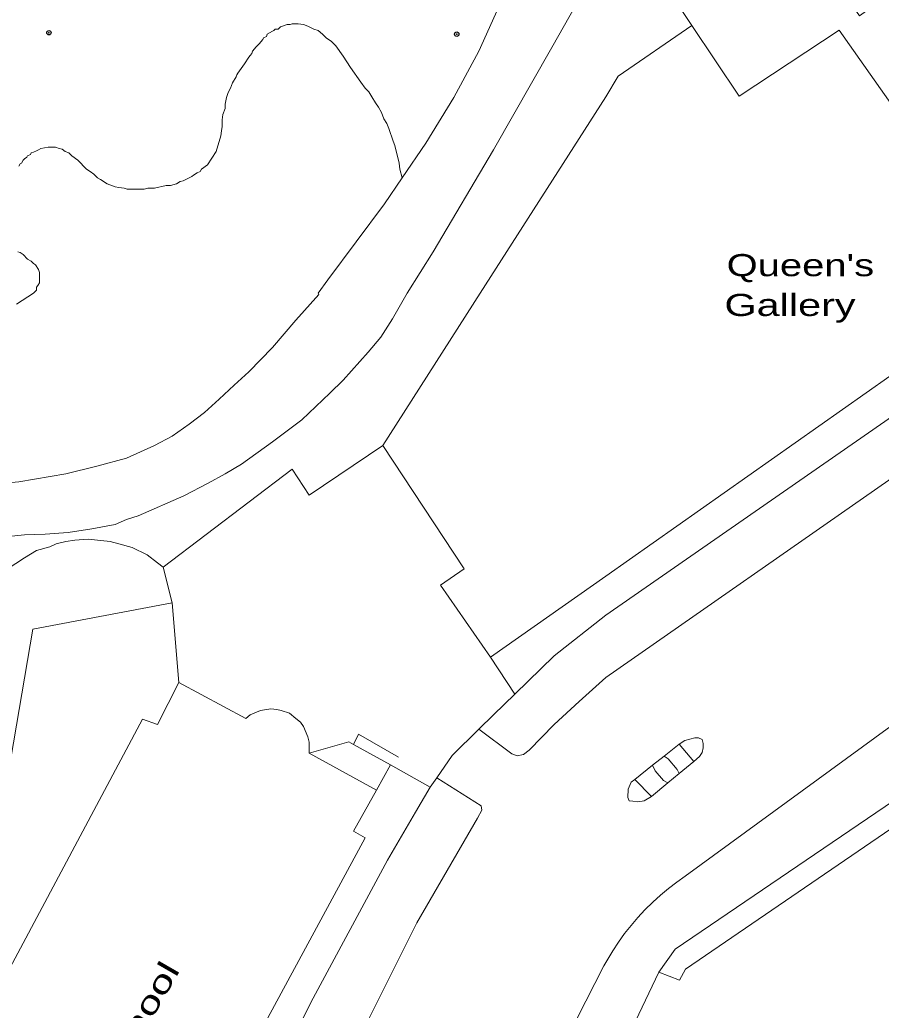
# Model space of a CAD drawing. Extents: x 528790 to 529292, y 179350 to 179856.
# Drawn here: x 528960.3 to 529018.7, y 179451.4 to 179518.5 of the extents above; entities that cross this region are included whole.
import ezdxf

# ---------------------------------------------------------------- set-up
doc = ezdxf.new("R2010")
doc.units = 0
doc.header["$LTSCALE"] = 0.6
doc.header["$PDMODE"] = 32
doc.header["$PDSIZE"] = 0.3
doc.layers.add('1', color=7, linetype='Continuous', lineweight=13)
doc.layers.add('2', color=7, linetype='Continuous', lineweight=13)
doc.layers.add('3', color=7, linetype='Continuous')
doc.layers.add('5', color=7, linetype='Continuous')

msp = doc.modelspace()

# ---------------------------------------------------------------- linework, layer by layer
at = {"layer": '1'}
for points in [[(529073.95, 179531.9), (529070.6, 179529.65), (529065.42, 179526.17), (529064.07, 179524.62), (529047.17, 179512.85), (529035.4, 179502.75), (529031.5, 179500), (529020.564, 179492.414), (529000, 179478.15), (528996.5, 179475.4), (528993.832, 179472.797), (528992.4, 179471.4), (528991.407, 179470.425), (528993.641, 179468.76), (528994.001, 179468.622), (528994.425, 179468.717), (528994.8, 179469), (528996.5, 179470.75), (528998.2, 179472.3), (529000, 179473.93), (529019.2, 179487.3), (529029.2, 179494.15), (529037.35, 179500), (529076.8, 179527.1)], [(529076.8, 179527.1), (529037.35, 179500), (529029.2, 179494.15), (529019.2, 179487.3), (529000, 179473.93), (528998.2, 179472.3), (528996.5, 179470.75), (528994.8, 179469), (528994.425, 179468.717), (528994.001, 179468.622), (528993.641, 179468.76), (528991.407, 179470.425), (528989.6, 179468.65), (528988.542, 179467.133), (528991.564, 179465.226), (528991.609, 179464.932), (528991.3, 179464.4), (528987.2, 179457.3), (528981.95, 179446.8)], [(528995.6, 179525.75), (528991.4, 179516.4), (528989.7, 179513.25), (528987.8, 179510.15), (528986.2, 179507.8), (528985, 179506.05), (528981.15, 179500.9), (528980.5, 179500), (528980.55, 179499.9), (528979, 179498.15), (528977.4, 179496.3), (528975.8, 179494.65), (528974.8, 179493.75), (528973.8, 179492.8), (528972.8, 179491.9), (528971.75, 179491.1), (528970.6, 179490.3), (528969.4, 179489.65), (528967.5, 179488.8), (528965.5, 179488.25), (528963.4, 179487.75), (528960.2, 179487.2)], [(528965.55, 179507.8), (528965.75, 179507.7), (528966.2, 179507.4), (528966.75, 179507.2), (528967, 179507.15), (528967.35, 179507.1), (528967.55, 179507.05), (528968.7, 179507.05), (528968.95, 179507.1), (528969.4, 179507.1), (528970.2, 179507.3), (528970.5, 179507.3), (528970.9, 179507.4), (528971.15, 179507.55), (528971.35, 179507.6), (528971.95, 179507.9), (528972.05, 179508), (528972.3, 179508.15), (528972.5, 179508.25), (528972.6, 179508.4), (528973, 179508.7), (528973.6, 179509.6), (528973.9, 179510.65), (528973.95, 179511), (528974, 179511.3), (528974, 179511.75), (528974.05, 179512.1), (528974.2, 179512.5), (528974.2, 179512.8), (528974.3, 179513.25), (528974.4, 179513.6), (528974.55, 179513.9), (528974.7, 179514.25), (528974.95, 179514.65), (528975, 179514.8), (528975.05, 179514.9), (528975.5, 179515.55), (528975.8, 179516), (528975.9, 179516.1), (528976, 179516.25), (528976.05, 179516.4), (528976.3, 179516.7), (528976.5, 179516.9), (528976.75, 179517.2), (528976.8, 179517.3), (528977, 179517.4), (528977.05, 179517.55), (528977.4, 179517.75), (528977.5, 179517.8), (528977.6, 179517.9), (528977.8, 179517.9), (528977.95, 179518.05), (528978.4, 179518.2), (528978.6, 179518.2), (528978.75, 179518.25), (528979.15, 179518.25), (528979.5, 179518.2), (528979.8, 179518.1), (528980.2, 179517.9), (528980.5, 179517.8), (528980.8, 179517.55), (528981.05, 179517.3), (528981.4, 179517.05), (528981.7, 179516.75), (528982.2, 179516.05), (528982.7, 179515.3), (528983.4, 179514.3), (528983.7, 179513.9), (528983.95, 179513.65), (528984.15, 179513.3), (528984.4, 179512.9), (528984.6, 179512.6), (528984.8, 179512.25), (528984.95, 179511.8), (528985.15, 179511.5), (528985.3, 179511.15), (528985.6, 179510.3), (528985.7, 179510), (528986, 179508.8), (528986.05, 179508.4), (528986.2, 179507.8), (528987.8, 179510.15), (528989.7, 179513.25), (528991.4, 179516.4), (528995.6, 179525.75)], [(528978.75, 179488.05), (528979.9, 179486.3), (528984.9, 179489.65), (528991.5, 179500), (529000, 179513.3), (529000.85, 179514.7), (529005.85, 179518.14), (529001.81, 179524.22), (529004.05, 179525.81)], [(528998.75, 179520.9), (528996.35, 179516.65), (528992.4, 179509.7), (528988.3, 179502.8), (528986.55, 179500), (528985.55, 179498.25), (528984.75, 179497), (528983.9, 179496), (528982.2, 179494.1), (528981.3, 179493.2), (528979.4, 179491.4), (528977.4, 179489.9), (528975.3, 179488.4), (528974.2, 179487.75), (528973.05, 179487.1), (528971.4, 179486.25), (528968.3, 179484.9), (528967.5, 179484.65), (528966.75, 179484.3), (528965.15, 179484), (528963.55, 179483.75), (528962, 179483.65), (528960.6, 179483.6), (528957.7, 179483.3)], [(528992.4, 179509.7), (528996.35, 179516.65), (528998.75, 179520.9)], [(528986.2, 179507.8), (528986.05, 179508.4), (528986, 179508.8), (528985.7, 179510), (528985.6, 179510.3), (528985.3, 179511.15), (528985.15, 179511.5), (528984.95, 179511.8), (528984.8, 179512.25), (528984.6, 179512.6), (528984.4, 179512.9), (528984.15, 179513.3), (528983.95, 179513.65), (528983.7, 179513.9), (528983.4, 179514.3), (528982.7, 179515.3), (528982.2, 179516.05), (528981.7, 179516.75), (528981.4, 179517.05), (528981.05, 179517.3), (528980.8, 179517.55), (528980.5, 179517.8), (528980.2, 179517.9), (528979.8, 179518.1), (528979.5, 179518.2), (528979.15, 179518.25), (528978.75, 179518.25), (528978.6, 179518.2), (528978.4, 179518.2), (528977.95, 179518.05), (528977.8, 179517.9), (528977.6, 179517.9), (528977.5, 179517.8), (528977.4, 179517.75), (528977.05, 179517.55), (528977, 179517.4), (528976.8, 179517.3), (528976.75, 179517.2), (528976.5, 179516.9), (528976.3, 179516.7), (528976.05, 179516.4), (528976, 179516.25), (528975.9, 179516.1), (528975.8, 179516), (528975.5, 179515.55), (528975.05, 179514.9), (528975, 179514.8), (528974.95, 179514.65), (528974.7, 179514.25), (528974.55, 179513.9), (528974.4, 179513.6), (528974.3, 179513.25), (528974.2, 179512.8), (528974.2, 179512.5), (528974.05, 179512.1), (528974, 179511.75), (528974, 179511.3), (528973.95, 179511), (528973.9, 179510.65), (528973.6, 179509.6), (528973, 179508.7), (528972.6, 179508.4), (528972.5, 179508.25), (528972.3, 179508.15), (528972.05, 179508), (528971.95, 179507.9), (528971.35, 179507.6), (528971.15, 179507.55), (528970.9, 179507.4), (528970.5, 179507.3), (528970.2, 179507.3), (528969.4, 179507.1), (528968.95, 179507.1), (528968.7, 179507.05), (528967.55, 179507.05), (528967.35, 179507.1), (528967, 179507.15), (528966.75, 179507.2), (528966.2, 179507.4), (528965.75, 179507.7), (528965.55, 179507.8), (528965.3, 179508.05), (528965.05, 179508.25), (528964.8, 179508.4), (528964.2, 179509), (528963.8, 179509.3), (528963.6, 179509.5), (528963.35, 179509.6), (528963.15, 179509.75), (528962.95, 179509.8), (528962.7, 179509.9), (528962.2, 179509.9), (528961.7, 179509.8), (528961.55, 179509.7), (528961.4, 179509.65), (528961.2, 179509.55), (528961.05, 179509.5), (528961, 179509.4), (528960.8, 179509.3), (528960.75, 179509.2), (528960.6, 179509.1)], [(528957.7, 179483.3), (528960.6, 179483.6), (528962, 179483.65), (528963.55, 179483.75), (528965.15, 179484), (528966.75, 179484.3), (528967.5, 179484.65), (528968.3, 179484.9), (528971.4, 179486.25), (528973.05, 179487.1), (528974.2, 179487.75), (528975.3, 179488.4), (528977.4, 179489.9), (528979.4, 179491.4), (528981.3, 179493.2), (528982.2, 179494.1), (528983.9, 179496), (528984.75, 179497), (528985.55, 179498.25), (528986.55, 179500), (528988.3, 179502.8), (528992.4, 179509.7)], [(528960.2, 179508.6), (528960.3, 179508.75), (528960.4, 179508.8), (528960.5, 179509), (528960.6, 179509.1), (528960.75, 179509.2), (528960.8, 179509.3), (528961, 179509.4), (528961.05, 179509.5), (528961.2, 179509.55), (528961.4, 179509.65), (528961.55, 179509.7), (528961.7, 179509.8), (528962.2, 179509.9), (528962.7, 179509.9), (528962.95, 179509.8), (528963.15, 179509.75), (528963.35, 179509.6), (528963.6, 179509.5), (528963.8, 179509.3), (528964.2, 179509), (528964.8, 179508.4), (528965.05, 179508.25), (528965.3, 179508.05), (528965.55, 179507.8)], [(528960.6, 179509.1), (528960.5, 179509), (528960.4, 179508.8), (528960.3, 179508.75), (528960.2, 179508.6)], [(528960.2, 179487.2), (528963.4, 179487.75), (528965.5, 179488.25), (528967.5, 179488.8), (528969.4, 179489.65), (528970.6, 179490.3), (528971.75, 179491.1), (528972.8, 179491.9), (528973.8, 179492.8), (528974.8, 179493.75), (528975.8, 179494.65), (528977.4, 179496.3), (528979, 179498.15), (528980.55, 179499.9), (528980.5, 179500), (528981.15, 179500.9), (528985, 179506.05), (528986.2, 179507.8)], [(528960.15, 179502.8), (528960.3, 179502.75), (528960.5, 179502.6), (528960.8, 179502.3), (528961.05, 179502.15), (528961.2, 179502), (528961.35, 179501.9), (528961.55, 179501.6), (528961.6, 179501.4), (528961.6, 179500.7), (528961.5, 179500.5), (528961.4, 179500.4), (528961.4, 179500.2), (528961.2, 179500), (528960.05, 179499.25)], [(528960.05, 179499.25), (528961.2, 179500), (528961.4, 179500.2), (528961.4, 179500.4), (528961.5, 179500.5), (528961.6, 179500.7), (528961.6, 179501.4), (528961.55, 179501.6), (528961.35, 179501.9), (528961.2, 179502), (528961.05, 179502.15), (528960.8, 179502.3), (528960.5, 179502.6), (528960.3, 179502.75), (528960.15, 179502.8)], [(529054.064, 179495.965), (529005.396, 179460.457), (529004.818, 179460.049), (529004.258, 179459.618), (529003.715, 179459.164), (529003.191, 179458.689), (529002.664, 179458.169), (529002.182, 179457.652), (529001.721, 179457.116), (529001.282, 179456.561), (529000.866, 179455.989), (529000.474, 179455.4)], [(529002.182, 179457.652), (529002.664, 179458.169), (529003.191, 179458.689), (529003.715, 179459.164), (529004.258, 179459.618), (529004.818, 179460.049), (529005.396, 179460.457), (529054.064, 179495.965)], [(529075.3, 179473.5), (529070.95, 179475.45), (529069.75, 179474.35), (529069.6, 179474.25), (529068.05, 179473.3), (529056.9, 179489.3), (529033.45, 179473.3), (529032.85, 179472.9), (529030, 179470.95), (529029.25, 179470.45), (529005.4, 179454.15), (529005, 179453.4), (529003.6, 179453.95), (529000, 179446.4)], [(528958.8, 179480.9), (528960.6, 179482.05), (528961.4, 179482.55), (528962.3, 179482.8), (528962.75, 179483), (528963.4, 179483.15), (528964, 179483.25), (528964.9, 179483.3), (528966.4, 179483.15), (528967, 179483), (528967.9, 179482.75), (528968.9, 179482.25), (528969.6, 179481.7), (528970, 179481.4), (528978.75, 179488.05)], [(528957.8, 179457.55), (528961.15, 179477.2), (528970.6, 179479), (528970, 179481.4), (528969.6, 179481.7), (528968.9, 179482.25), (528967.9, 179482.75), (528967, 179483), (528966.4, 179483.15), (528964.9, 179483.3), (528964, 179483.25), (528963.4, 179483.15), (528962.75, 179483), (528962.3, 179482.8), (528961.4, 179482.55), (528960.6, 179482.05), (528958.8, 179480.9)], [(528972.3, 179442), (528983.7, 179463.05), (528982.9, 179463.5), (528984.45, 179466.3), (528979.9, 179468.8), (528979.9, 179469.55), (528979.8, 179469.9), (528979.5, 179470.6), (528979.3, 179470.9), (528979, 179471.15), (528978.55, 179471.5), (528978, 179471.7), (528977.7, 179471.75), (528977.3, 179471.8), (528976.6, 179471.7), (528975.9, 179471.4), (528975.6, 179471.15), (528971.05, 179473.6), (528969.6, 179470.75), (528968.6, 179471.1), (528957.35, 179450.05)], [(529000, 179446.4), (529003.6, 179453.95), (529004.7, 179455.5), (529028.4, 179471.6)], [(528981.95, 179446.8), (528987.2, 179457.3), (528991.3, 179464.4), (528991.609, 179464.932), (528991.564, 179465.226), (528988.542, 179467.133), (528988.1, 179466.5), (528987.1, 179464.8), (528985.2, 179461.55), (528980, 179451.9), (528974.1, 179440.05)], [(528996.2, 179447.15), (528999.866, 179454.369), (529000.474, 179455.4), (529000.866, 179455.989), (529001.282, 179456.561), (529001.721, 179457.116), (529002.182, 179457.652)], [(529000.474, 179455.4), (528999.866, 179454.369), (528996.2, 179447.15)]]:
    msp.add_lwpolyline(points, dxfattribs=at)
for points in [[(529010.352, 179528.732), (529008.022, 179527.132), (529007.33, 179528.14), (529004.05, 179525.81), (529001.81, 179524.22), (529005.85, 179518.14), (529009.04, 179513.34), (529015.84, 179517.83), (529028.02, 179500.54), (529034, 179504.75), (529030.07, 179510.45), (529027.29, 179514.43), (529026.2, 179516), (529024.35, 179518.8), (529022, 179522.25), (529017.2, 179518.8)], [(529005.85, 179518.14), (529000.85, 179514.7), (529000, 179513.3), (528991.5, 179500), (528984.9, 179489.65), (528990.4, 179481.3), (528988.8, 179480.2), (528992.2, 179475.3), (529000, 179480.8), (529019.256, 179494.368), (529027.25, 179500), (529028.02, 179500.54), (529015.84, 179517.83), (529009.04, 179513.34)], [(528996.5, 179475.4), (529000, 179478.15), (529020.564, 179492.414), (529019.256, 179494.368), (529000, 179480.8), (528992.2, 179475.3), (528993.832, 179472.797)], [(528992.2, 179475.3), (528988.8, 179480.2), (528990.4, 179481.3), (528984.9, 179489.65), (528979.9, 179486.3), (528978.75, 179488.05), (528970, 179481.4), (528970.6, 179479), (528971.05, 179473.6), (528975.6, 179471.15), (528975.9, 179471.4), (528976.6, 179471.7), (528977.3, 179471.8), (528977.7, 179471.75), (528978, 179471.7), (528978.55, 179471.5), (528979, 179471.15), (528979.3, 179470.9), (528979.5, 179470.6), (528979.8, 179469.9), (528979.9, 179469.55), (528979.9, 179468.8), (528982.592, 179469.56), (528982.905, 179469.386), (528985.4, 179468), (528988.1, 179466.5), (528988.542, 179467.133), (528989.6, 179468.65), (528991.407, 179470.425), (528992.4, 179471.4), (528993.832, 179472.797)], [(528971.05, 179473.6), (528970.6, 179479), (528961.15, 179477.2), (528957.8, 179457.55), (528956.2, 179454.6), (528951.98, 179456.87), (528951.49, 179455.7), (528943.42, 179446.38), (528938.74, 179442.76), (528935.52, 179441.13), (528932.41, 179439.47), (528932.4, 179437.9), (528937.76, 179423), (528941.48, 179421.16), (528949.6, 179436.1), (528949.55, 179436.55), (528956.8, 179450), (528957.35, 179450.05), (528968.6, 179471.1), (528969.6, 179470.75)], [(529005.4, 179454.15), (529029.25, 179470.45), (529028.4, 179471.6), (529004.7, 179455.5), (529003.6, 179453.95), (529005, 179453.4)], [(529004.99, 179469.415), (529005.372, 179469.651), (529006.048, 179469.827), (529006.283, 179469.827), (529006.542, 179469.733), (529006.6, 179469.453), (529006.607, 179469.151), (529006.547, 179468.851), (529006.371, 179468.563), (529005.98, 179468.239), (529004.991, 179467.419), (529004.219, 179466.779), (529003.109, 179465.859), (529002.599, 179465.57), (529002.169, 179465.506), (529001.845, 179465.536), (529001.581, 179465.565), (529001.493, 179465.8), (529001.522, 179466.359), (529001.728, 179466.829), (529001.972, 179467.022), (529003.182, 179467.981), (529003.964, 179468.602)], [(529006.371, 179468.563), (529006.547, 179468.851), (529006.607, 179469.151), (529006.6, 179469.453), (529006.542, 179469.733), (529006.283, 179469.827), (529006.048, 179469.827), (529005.372, 179469.651), (529004.99, 179469.415), (529005.98, 179468.239)], [(528985.4, 179468), (528982.905, 179469.386), (528982.592, 179469.56), (528979.9, 179468.8), (528984.45, 179466.3)], [(529005.98, 179468.239), (529004.99, 179469.415), (529003.964, 179468.602), (529004.242, 179468.41), (529004.841, 179467.697), (529004.991, 179467.419)], [(529004.219, 179466.779), (529004.991, 179467.419), (529004.841, 179467.697), (529004.242, 179468.41), (529003.964, 179468.602), (529003.182, 179467.981), (529003.349, 179467.607), (529003.914, 179466.94)], [(528980, 179451.9), (528985.2, 179461.55), (528987.1, 179464.8), (528988.1, 179466.5), (528985.4, 179468), (528984.45, 179466.3), (528982.9, 179463.5), (528983.7, 179463.05), (528972.3, 179442), (528972.4, 179441.7), (528972.05, 179441.05), (528972.85, 179440.65), (528974.1, 179440.05)], [(529004.219, 179466.779), (529003.914, 179466.94), (529003.349, 179467.607), (529003.182, 179467.981), (529001.972, 179467.022), (529003.109, 179465.859)], [(529003.109, 179465.859), (529001.972, 179467.022), (529001.728, 179466.829), (529001.522, 179466.359), (529001.493, 179465.8), (529001.581, 179465.565), (529001.845, 179465.536), (529002.169, 179465.506), (529002.599, 179465.57)]]:
    msp.add_lwpolyline(points, close=True, dxfattribs=at)
at = {"layer": '2'}
for p, q in [((528984.9, 179489.65), (528990.4, 179481.3)), ((528970.6, 179479), (528970, 179481.4)), ((528970.6, 179479), (528971.05, 179473.6)), ((528992.2, 179475.3), (528993.832, 179472.797)), ((528985.4, 179468), (528982.905, 179469.386)), ((529003.964, 179468.602), (529004.99, 179469.415)), ((529004.99, 179469.415), (529005.98, 179468.239)), ((528984.45, 179466.3), (528979.9, 179468.8)), ((529003.182, 179467.981), (529003.964, 179468.602)), ((528985.4, 179468), (528984.45, 179466.3)), ((528988.1, 179466.5), (528985.4, 179468)), ((529001.972, 179467.022), (529003.182, 179467.981)), ((529005.98, 179468.239), (529004.991, 179467.419)), ((528988.542, 179467.133), (528988.1, 179466.5)), ((529004.991, 179467.419), (529004.219, 179466.779)), ((529001.972, 179467.022), (529003.109, 179465.859)), ((529004.219, 179466.779), (529003.109, 179465.859))]:
    msp.add_line(p, q, dxfattribs=at)
for points in [[(528980.41, 179553.09), (528989.4, 179540.2), (528995.55, 179531.05), (528996.2, 179529.55), (528996.2, 179528.5), (528996, 179527.4), (528995.8, 179526.55), (528995.6, 179525.75), (528991.4, 179516.4), (528989.7, 179513.25), (528987.8, 179510.15), (528986.2, 179507.8)], [(529075.4, 179532.9), (529077.2, 179530.3), (529077.4, 179530.05), (529077.5, 179529.75), (529077.5, 179528.55), (529077.25, 179527.8), (529077.05, 179527.4), (529076.8, 179527.1), (529037.35, 179500), (529029.2, 179494.15), (529019.2, 179487.3), (529000, 179473.93), (528998.2, 179472.3), (528996.5, 179470.75), (528994.8, 179469), (528994.425, 179468.717), (528994.001, 179468.622), (528993.641, 179468.76), (528991.407, 179470.425)], [(529004.05, 179525.81), (529001.81, 179524.22), (529005.85, 179518.14)], [(528998.75, 179520.9), (528996.35, 179516.65), (528992.4, 179509.7), (528988.3, 179502.8), (528986.55, 179500), (528985.55, 179498.25), (528984.75, 179497), (528983.9, 179496), (528982.2, 179494.1), (528981.3, 179493.2), (528979.4, 179491.4), (528977.4, 179489.9), (528975.3, 179488.4), (528974.2, 179487.75), (528973.05, 179487.1), (528971.4, 179486.25), (528968.3, 179484.9), (528967.5, 179484.65), (528966.75, 179484.3), (528965.15, 179484), (528963.55, 179483.75), (528962, 179483.65), (528960.6, 179483.6), (528957.7, 179483.3)], [(528986.2, 179507.8), (528986.05, 179508.4), (528986, 179508.8), (528985.7, 179510), (528985.6, 179510.3), (528985.3, 179511.15), (528985.15, 179511.5), (528984.95, 179511.8), (528984.8, 179512.25), (528984.6, 179512.6), (528984.4, 179512.9), (528984.15, 179513.3), (528983.95, 179513.65), (528983.7, 179513.9), (528983.4, 179514.3), (528982.7, 179515.3), (528982.2, 179516.05), (528981.7, 179516.75), (528981.4, 179517.05), (528981.05, 179517.3), (528980.8, 179517.55), (528980.5, 179517.8), (528980.2, 179517.9), (528979.8, 179518.1), (528979.5, 179518.2), (528979.15, 179518.25), (528978.75, 179518.25), (528978.6, 179518.2), (528978.4, 179518.2), (528977.95, 179518.05), (528977.8, 179517.9), (528977.6, 179517.9), (528977.5, 179517.8), (528977.4, 179517.75), (528977.05, 179517.55), (528977, 179517.4), (528976.8, 179517.3), (528976.75, 179517.2), (528976.5, 179516.9), (528976.3, 179516.7), (528976.05, 179516.4), (528976, 179516.25), (528975.9, 179516.1), (528975.8, 179516), (528975.5, 179515.55), (528975.05, 179514.9), (528975, 179514.8), (528974.95, 179514.65), (528974.7, 179514.25), (528974.55, 179513.9), (528974.4, 179513.6), (528974.3, 179513.25), (528974.2, 179512.8), (528974.2, 179512.5), (528974.05, 179512.1), (528974, 179511.75), (528974, 179511.3), (528973.95, 179511), (528973.9, 179510.65), (528973.6, 179509.6), (528973, 179508.7), (528972.6, 179508.4), (528972.5, 179508.25), (528972.3, 179508.15), (528972.05, 179508), (528971.95, 179507.9), (528971.35, 179507.6), (528971.15, 179507.55), (528970.9, 179507.4), (528970.5, 179507.3), (528970.2, 179507.3), (528969.4, 179507.1), (528968.95, 179507.1), (528968.7, 179507.05), (528967.55, 179507.05), (528967.35, 179507.1), (528967, 179507.15), (528966.75, 179507.2), (528966.2, 179507.4), (528965.75, 179507.7), (528965.55, 179507.8), (528965.3, 179508.05), (528965.05, 179508.25), (528964.8, 179508.4), (528964.2, 179509), (528963.8, 179509.3), (528963.6, 179509.5), (528963.35, 179509.6), (528963.15, 179509.75), (528962.95, 179509.8), (528962.7, 179509.9), (528962.2, 179509.9), (528961.7, 179509.8), (528961.55, 179509.7), (528961.4, 179509.65), (528961.2, 179509.55), (528961.05, 179509.5), (528961, 179509.4), (528960.8, 179509.3), (528960.75, 179509.2), (528960.6, 179509.1)], [(529005.85, 179518.14), (529000.85, 179514.7), (529000, 179513.3), (528991.5, 179500), (528984.9, 179489.65)], [(529028.02, 179500.54), (529015.84, 179517.83), (529009.04, 179513.34), (529005.85, 179518.14)], [(528960.6, 179509.1), (528960.5, 179509), (528960.4, 179508.8), (528960.3, 179508.75), (528960.2, 179508.6)], [(528986.2, 179507.8), (528985, 179506.05), (528981.15, 179500.9), (528980.5, 179500), (528980.55, 179499.9), (528979, 179498.15), (528977.4, 179496.3), (528975.8, 179494.65), (528974.8, 179493.75), (528973.8, 179492.8), (528972.8, 179491.9), (528971.75, 179491.1), (528970.6, 179490.3), (528969.4, 179489.65), (528967.5, 179488.8), (528965.5, 179488.25), (528963.4, 179487.75), (528960.2, 179487.2), (528957, 179486.9), (528952.6, 179486.9), (528951.65, 179486.95)], [(528960.15, 179502.8), (528960.3, 179502.75), (528960.5, 179502.6), (528960.8, 179502.3), (528961.05, 179502.15), (528961.2, 179502), (528961.35, 179501.9), (528961.55, 179501.6), (528961.6, 179501.4), (528961.6, 179500.7), (528961.5, 179500.5), (528961.4, 179500.4), (528961.4, 179500.2), (528961.2, 179500), (528960.05, 179499.25)], [(528996.2, 179447.15), (528999.866, 179454.369), (529000.474, 179455.4), (529000.866, 179455.989), (529001.282, 179456.561), (529001.721, 179457.116), (529002.182, 179457.652), (529002.664, 179458.169), (529003.191, 179458.689), (529003.715, 179459.164), (529004.258, 179459.618), (529004.818, 179460.049), (529005.396, 179460.457), (529054.064, 179495.965)], [(529019.256, 179494.368), (529000, 179480.8), (528992.2, 179475.3)], [(529020.564, 179492.414), (529000, 179478.15), (528996.5, 179475.4), (528993.832, 179472.797)], [(528984.9, 179489.65), (528979.9, 179486.3), (528978.75, 179488.05), (528970, 179481.4)], [(528970, 179481.4), (528969.6, 179481.7), (528968.9, 179482.25), (528967.9, 179482.75), (528967, 179483), (528966.4, 179483.15), (528964.9, 179483.3), (528964, 179483.25), (528963.4, 179483.15), (528962.75, 179483), (528962.3, 179482.8), (528961.4, 179482.55), (528960.6, 179482.05), (528958.8, 179480.9)], [(528992.2, 179475.3), (528988.8, 179480.2), (528990.4, 179481.3)], [(528951.98, 179456.87), (528956.2, 179454.6), (528957.8, 179457.55), (528961.15, 179477.2), (528970.6, 179479)], [(528941.48, 179421.16), (528949.6, 179436.1), (528949.55, 179436.55), (528956.8, 179450), (528957.35, 179450.05), (528968.6, 179471.1), (528969.6, 179470.75), (528971.05, 179473.6)], [(528971.05, 179473.6), (528975.6, 179471.15), (528975.9, 179471.4), (528976.6, 179471.7), (528977.3, 179471.8), (528977.7, 179471.75), (528978, 179471.7), (528978.55, 179471.5), (528979, 179471.15), (528979.3, 179470.9), (528979.5, 179470.6), (528979.8, 179469.9), (528979.9, 179469.55), (528979.9, 179468.8)], [(528993.832, 179472.797), (528992.4, 179471.4), (528991.407, 179470.425)], [(529003.6, 179453.95), (529004.7, 179455.5), (529028.4, 179471.6)], [(528991.407, 179470.425), (528989.6, 179468.65), (528988.542, 179467.133)], [(529029.25, 179470.45), (529005.4, 179454.15), (529005, 179453.4), (529003.6, 179453.95)], [(528982.905, 179469.386), (528983.249, 179470.097), (528985.951, 179468.533)], [(529004.99, 179469.415), (529005.372, 179469.651), (529006.048, 179469.827), (529006.283, 179469.827), (529006.542, 179469.733), (529006.6, 179469.453), (529006.607, 179469.151), (529006.547, 179468.851), (529006.371, 179468.563), (529005.98, 179468.239)], [(528982.905, 179469.386), (528982.592, 179469.56), (528979.9, 179468.8)], [(529003.964, 179468.602), (529004.242, 179468.41), (529004.841, 179467.697), (529004.991, 179467.419)], [(529004.219, 179466.779), (529003.914, 179466.94), (529003.349, 179467.607), (529003.182, 179467.981)], [(528988.542, 179467.133), (528991.564, 179465.226), (528991.609, 179464.932), (528991.3, 179464.4), (528987.2, 179457.3), (528981.95, 179446.8), (528981.31, 179445.48)], [(528988.1, 179466.5), (528987.1, 179464.8), (528985.2, 179461.55), (528980, 179451.9), (528974.1, 179440.05)], [(529003.109, 179465.859), (529002.599, 179465.57), (529002.169, 179465.506), (529001.845, 179465.536), (529001.581, 179465.565), (529001.493, 179465.8), (529001.522, 179466.359), (529001.728, 179466.829), (529001.972, 179467.022)], [(528972.05, 179441.05), (528972.4, 179441.7), (528972.3, 179442), (528983.7, 179463.05), (528982.9, 179463.5), (528984.45, 179466.3)], [(529003.6, 179453.95), (529000, 179446.4), (528997.55, 179441.25), (528998.5, 179439.6), (529000, 179438.93), (529007.7, 179436.45)]]:
    msp.add_lwpolyline(points, dxfattribs=at)
at = {"layer": '3'}
for p in [(528962.25, 179517.65), (528989.9, 179517.55)]:
    msp.add_point(p, dxfattribs=at)

# ---------------------------------------------------------------- texts
at = {"layer": '5'}
for s, width, p in [("Queen's", 1.35, (529008.2, 179501.14)), ('Gallery', 1.4, (529008.05, 179498.44))]:
    msp.add_text(s, height=1.5, dxfattribs=dict(at, width=width)).set_placement(p)
at = {"layer": '5', "width": 1.45}
msp.add_text('Riding School', height=1.5, rotation=60, dxfattribs=at).set_placement((528962.2, 179438.55))

doc.saveas('drawing.dxf')
